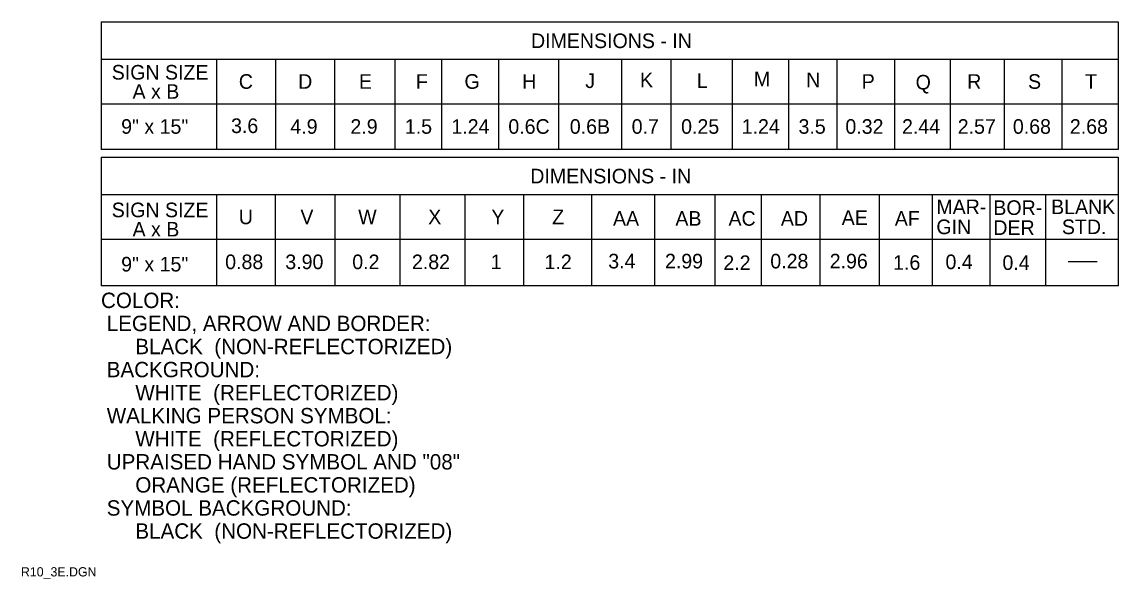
# Model space of a CAD drawing. Extents: x 0.013 to 0.191, y 0.004 to 0.259.
# Drawn here: x 0.0125 to 0.1905, y 0.0038 to 0.0944 of the extents above; entities that cross this region are included whole.
import ezdxf

# ---------------------------------------------------------------- set-up
doc = ezdxf.new("R2010")
doc.units = 0
doc.layers.add('1', color=7, linetype='Continuous')
doc.layers.add('3', color=7, linetype='Continuous')

msp = doc.modelspace()

# ---------------------------------------------------------------- linework, layer by layer
at = {"layer": '3'}
for p, q in [((0.02538, 0.09438), (0.02538, 0.07362)), ((0.02538, 0.09438), (0.1905, 0.09438)), ((0.1905, 0.09438), (0.1905, 0.07362)), ((0.1905, 0.08825), (0.02538, 0.08825)), ((0.04412, 0.08816), (0.04412, 0.07365)), ((0.0537, 0.0882), (0.0537, 0.07369)), ((0.06329, 0.0882), (0.06329, 0.07369)), ((0.07306, 0.08816), (0.07306, 0.07365)), ((0.08065, 0.08827), (0.08065, 0.07376)), ((0.08991, 0.08816), (0.08991, 0.07365)), ((0.09967, 0.08816), (0.09967, 0.07365)), ((0.1099, 0.08816), (0.1099, 0.07365)), ((0.11787, 0.08817), (0.11787, 0.07365)), ((0.12785, 0.08825), (0.12785, 0.07374)), ((0.13702, 0.08817), (0.13702, 0.07365)), ((0.14486, 0.08817), (0.14486, 0.07365)), ((0.15419, 0.08817), (0.15419, 0.07365)), ((0.16324, 0.08817), (0.16324, 0.07365)), ((0.17203, 0.08817), (0.17203, 0.07365)), ((0.18137, 0.08817), (0.18137, 0.07365)), ((0.1905, 0.081), (0.02538, 0.081)), ((0.1905, 0.07362), (0.02538, 0.07362)), ((0.02538, 0.07237), (0.02538, 0.0515)), ((0.02538, 0.07237), (0.1905, 0.07237)), ((0.1905, 0.07237), (0.1905, 0.0515)), ((0.1905, 0.06625), (0.02538, 0.06625)), ((0.04412, 0.06619), (0.04412, 0.05144)), ((0.05363, 0.06619), (0.05363, 0.05144)), ((0.06336, 0.06619), (0.06336, 0.05144)), ((0.0739, 0.06619), (0.0739, 0.05144)), ((0.08445, 0.06619), (0.08445, 0.05144)), ((0.09399, 0.06625), (0.09399, 0.0515)), ((0.10501, 0.06625), (0.10501, 0.0515)), ((0.11526, 0.06619), (0.11526, 0.05144)), ((0.12503, 0.06619), (0.12503, 0.05144)), ((0.13257, 0.06619), (0.13257, 0.05144)), ((0.14208, 0.06619), (0.14208, 0.05144)), ((0.15174, 0.06619), (0.15174, 0.05144)), ((0.16031, 0.06616), (0.16031, 0.05153)), ((0.16966, 0.06616), (0.16966, 0.05153)), ((0.17873, 0.06616), (0.17873, 0.05153)), ((0.1905, 0.059), (0.02538, 0.059)), ((0.18713, 0.05538), (0.18238, 0.05538)), ((0.1905, 0.0515), (0.02538, 0.0515))]:
    msp.add_line(p, q, dxfattribs=at)

# ---------------------------------------------------------------- texts
at = {"layer": '1'}
for s, height, p in [('COLOR:', 0.0025, (0.02538, 0.04787)), (' LEGEND, ARROW AND BORDER:', 0.0024998, (0.02538, 0.04412)), ('      BLACK  (NON-REFLECTORIZED)', 0.0024998, (0.02538, 0.04037)), (' BACKGROUND:', 0.0024998, (0.02538, 0.03662)), ('      WHITE  (REFLECTORIZED)', 0.0024998, (0.02538, 0.03287)), (' WALKING PERSON SYMBOL:', 0.0024998, (0.02538, 0.02913)), ('      WHITE  (REFLECTORIZED)', 0.0024998, (0.02538, 0.02538)), (' UPRAISED HAND SYMBOL AND "08"', 0.0024998, (0.02538, 0.02163)), ('      ORANGE (REFLECTORIZED)', 0.0024998, (0.02538, 0.01788)), (' SYMBOL BACKGROUND:', 0.0024998, (0.02538, 0.01413)), ('      BLACK  (NON-REFLECTORIZED)', 0.0024998, (0.02538, 0.01038)), ('R10_3E.DGN', 0.0015, (0.01238, 0.00425))]:
    msp.add_text(s, height=height, dxfattribs=at).set_placement(p)
at = {"layer": '3'}
for s, height, p in [('DIMENSIONS - IN', 0.0023752, (0.09519, 0.09012)), ('SIGN SIZE', 0.002375, (0.02712, 0.085)), ('C', 0.00238, (0.04775, 0.0835)), ('D', 0.00238, (0.05738, 0.0835)), ('E', 0.00238, (0.06725, 0.0835)), ('F', 0.00238, (0.0765, 0.0835)), ('G', 0.00238, (0.08438, 0.0835)), ('H', 0.00238, (0.09375, 0.0835)), ('J', 0.00238, (0.104, 0.08363)), ('K', 0.00238, (0.11288, 0.08375)), ('L', 0.00238, (0.12212, 0.08363)), ('M', 0.00238, (0.13137, 0.08388)), ('N', 0.00238, (0.13987, 0.08375)), ('P', 0.00238, (0.14888, 0.0835)), ('Q', 0.00238, (0.15763, 0.08338)), ('R', 0.00238, (0.166, 0.0835)), ('S', 0.00238, (0.17588, 0.0835)), ('T', 0.00238, (0.18513, 0.0835)), ('A x B', 0.002375, (0.0305, 0.08188)), ('9" x 15"', 0.002375, (0.02865, 0.07619)), ('3.6', 0.002375, (0.04649, 0.07631)), ('4.9', 0.002375, (0.05612, 0.07619)), ('2.9', 0.002375, (0.06587, 0.07619)), ('1.5', 0.002375, (0.07471, 0.07619)), ('1.24', 0.002375, (0.08226, 0.07619)), ('0.6C', 0.002375, (0.09151, 0.07619)), ('0.6B', 0.002375, (0.10149, 0.07619)), ('0.7', 0.002375, (0.11153, 0.07619)), ('0.25', 0.002375, (0.11956, 0.07619)), ('1.24', 0.002375, (0.12939, 0.07619)), ('3.5', 0.002375, (0.13862, 0.07619)), ('0.32', 0.002375, (0.14623, 0.07619)), ('2.44', 0.002375, (0.15542, 0.07619)), ('2.57', 0.002375, (0.16447, 0.07619)), ('0.68', 0.002375, (0.17342, 0.07619)), ('2.68', 0.002375, (0.18267, 0.07619)), ('DIMENSIONS - IN', 0.0023752, (0.09507, 0.06813)), ('SIGN SIZE', 0.002375, (0.02712, 0.06263)), ('MAR-', 0.002375, (0.161, 0.06313)), ('BOR-', 0.002375, (0.17025, 0.063)), ('BLANK', 0.002375, (0.17963, 0.06313)), ('U', 0.00238, (0.04775, 0.0615)), ('V', 0.00238, (0.05775, 0.0615)), ('W', 0.00238, (0.06713, 0.0615)), ('X', 0.00238, (0.0785, 0.0615)), ('Y', 0.00238, (0.08875, 0.0615)), ('Z', 0.00238, (0.09863, 0.0615)), ('AA', 0.002375, (0.1085, 0.06125)), ('AB', 0.002375, (0.11863, 0.06125)), ('AC', 0.002375, (0.12725, 0.06125)), ('AD', 0.002375, (0.13575, 0.06125)), ('AE', 0.002375, (0.14563, 0.06137)), ('AF', 0.002375, (0.15425, 0.06125)), ('A x B', 0.002375, (0.0305, 0.0595)), ('GIN', 0.002375, (0.161, 0.05988)), ('DER', 0.002375, (0.17025, 0.05975)), ('STD.', 0.002375, (0.18138, 0.05988)), ('9" x 15"', 0.002375, (0.02865, 0.05381)), ('0.88', 0.002375, (0.04554, 0.05419)), ('3.90', 0.002375, (0.0553, 0.05419)), ('0.2', 0.002375, (0.06617, 0.05419)), ('2.82', 0.002375, (0.07586, 0.05419)), ('1', 0.00238, (0.08864, 0.05419)), ('1.2', 0.002375, (0.09739, 0.05419)), ('3.4', 0.002375, (0.10773, 0.05431)), ('2.99', 0.002375, (0.11694, 0.05431)), ('2.2', 0.002375, (0.12641, 0.05405)), ('0.28', 0.002375, (0.13404, 0.05431)), ('2.96', 0.002375, (0.14368, 0.05431)), ('1.6', 0.002375, (0.15398, 0.05408)), ('0.4', 0.002375, (0.16248, 0.05419)), ('0.4', 0.002375, (0.17173, 0.05406))]:
    msp.add_text(s, height=height, dxfattribs=at).set_placement(p)

doc.saveas('drawing.dxf')
